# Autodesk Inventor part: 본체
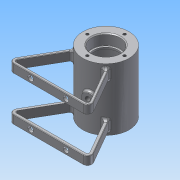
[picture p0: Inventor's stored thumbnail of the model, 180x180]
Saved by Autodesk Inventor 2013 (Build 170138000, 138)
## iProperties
Created: 2016-03
Part Number: 본체
Material: 알루미늄 6061
Document SubType Name: Modeling
Designer: Administrator
Density: 2.71 g/cm^3
Mass: 216.047 g
Surface Area: 342.935 cm^2
Volume: 79.7221 cm^3
Author: Administrator
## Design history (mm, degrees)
sketch "스케치1"
  geometry: C1 r 26 at (0, 0); 1 further point
  constraints: 1 centre point, 1 coincident
  dimensions: "d0" = 52 diameter of C1
extrude "돌출1" new body sketch "스케치1" stored distance "d1" = 70; taper "d2" = 0 deg
node "작업 평면1"
sketch "스케치2"
  geometry: L1 (0, 0)-(0, -62); L2 (-42.594, -62)-(42.594, -62); L3 (42.594, -62)-(0, 11.775); L4 (-42.594, -62)-(0, 11.775); C1 r 26 at (0, 0) reference; 1 further point
  constraints: 8 end point, 1 midpoint, 1 perpendicular, 1 vertical, 1 other
  dimensions: "d6" = 62 distance of L1.start L1.end; "d7" = 60 deg angle of L2 L3; "d8" = 85.18802 distance of L2.start L2.end
feature "리브1" sketch "스케치2" dims "d9" = 3, "d10" = 10, "d11" = 0, "d12" = 0, "d13" = 1, "d14" = 1
sketch "스케치3"
  geometry: C1 r 26 at (0, 0) reference; C2 r 21 at (0, 0); 1 further point
  constraints: 1 centre point, 1 coincident
  dimensions: "d15" = 42 diameter of C2
extrude "돌출2" cut sketch "스케치3" stored distance "d16" = 42; taper "d17" = 0 deg
sketch "스케치4"
  geometry: C1 r 26 at (0, 0) reference; C2 r 16 at (0, 0)
  constraints: 1 centre point, 1 coincident
  dimensions: "d18" = 32 diameter of C2
extrude "돌출3" cut sketch "스케치4" distance "d19" = 12; taper "d20" = 0 deg
sketch "스케치5"
  geometry: C1 r 16 at (0, 0) reference; C2 r 14 at (0, 0)
  constraints: 1 centre point, 1 coincident
  dimensions: "d21" = 28 diameter of C2
extrude "돌출4" cut sketch "스케치5" stored distance "d22" = 12; taper "d23" = 0 deg
node "작업 평면2"
sketch "스케치6"
  geometry: C1 r 5 at (0, 0); 1 further point
  constraints: 1 centre point, 1 coincident
  dimensions: "d25" = 10 diameter of C1
extrude "돌출5" join sketch "스케치6" stored distance "d26" = 12; taper "d27" = 0 deg
sketch "스케치7"
  geometry: L1 (-5, 25.515)-(-5, 29) reference; L2 (-5, 29)-(5, 29) reference; L3 (5, 29)-(5, 25.515) reference; L4 (0, 0)-(7.506, -28.012); L5 (0, 0)-(0, -50.543); C1 r 21 at (0, 0) reference; A1 r 26 centre (0, 0) between (-5, 25.515) and (5, 25.515) reference; 1 further point
  constraints: 4 end point, 1 parallel
  dimensions: "d28" = 29 distance of L4.start L4.end; "d29" = 15 deg angle of L4 L5
  node "절단 모서리 투영3"
node "작업 평면3"
sketch "스케치8"
  geometry: C1 r 6 at (0, 0); 1 further point
  constraints: 1 centre point, 1 coincident
  dimensions: "d30" = 12 diameter of C1
extrude "돌출6" join sketch "스케치8" stored distance "d31" = 12; taper "d32" = 0 deg
node "작업 평면4"
sketch "스케치9"
  geometry: L1 (-26, -35)-(-26, 35) reference; 2 further points
  constraints: 1 coincident, 1 other
feature "엠보싱1" sketch "스케치9" dims "d34" = 0.5, "d35" = 0
sketch "스케치10"
  geometry: C1 r 14 at (0, 0) reference; 1 further point
  constraints: 1 vertical alignment
  dimensions: "d36" = 21 distance of C1.centre point (0, 21)
hole "구멍1" sketch "스케치10" at (0, 21) diameter "d37" = 3.242; stored, may be unused: countersink angle "d41" = 90 deg, drill point angle "d43" = 118 deg; dims "d38" = 8, "d39" = 4, "d40" = 2, "d42" = 10
sketch "스케치11"
  geometry: C1 r 5 at (0, 0) reference
hole "구멍2" sketch "스케치11" at (0, 0) diameter "d47" = 5.188; stored, may be unused: countersink angle "d51" = 90 deg, drill point angle "d53" = 0 deg; dims "d48" = 50, "d49" = 4, "d50" = 2, "d52" = 10
sketch "스케치12"
  geometry: C1 r 6 at (0, 0) reference
hole "구멍3" sketch "스케치12" at (0, 0) diameter "d54" = 5.188; stored, may be unused: countersink angle "d58" = 90 deg, drill point angle "d60" = 0 deg; dims "d55" = 50, "d56" = 4, "d57" = 2, "d59" = 10
sketch "스케치13"
  geometry: 1 further point
fillet "모깎기1" dims "d61" = 3, "d62" = 0.3, "d63" = 5
fillet "모깎기2" dims "d64" = 2
sketch "스케치14"
  geometry: L1 (78.26, 0)-(0, 0) reference; L2 (0, 10)-(78.26, 10) reference; C1 r 3 at (19.13, 5); C2 r 3 at (59.13, 5); 1 further point
  constraints: 2 centre point
  dimensions: "d65" = 6 diameter of C1; "d66" = 6 diameter of C2; "d67" = 20 horizontal distance of point (39.13, -20) C1.centre; "d68" = 40 distance of C2.centre C1.centre; "d69" = 5 distance from line of C1.centre L2; "d70" = 5 distance from line of L1 C2.centre
extrude "돌출7" cut sketch "스케치14" stored distance "d71" = 12; taper "d72" = 0 deg
chamfer "모따기1" distance "d73" = 1; stored, may be unused: second distance "d74" = 2, angle "d75" = 45 deg
fillet "모깎기3" dims "d76" = 0.5
fillet "모깎기4" dims "d77" = 3
fillet "모깎기5" dims "d78" = 2
fillet "모깎기6" dims "d79" = 2
node "솔리드1"
mirror "대칭1"
pattern_circular "원형 패턴1" dims angle "d45" = 360 deg
mirror "대칭2"
mirror "대칭3"
mirror "대칭4"
node "절단 모서리 투영1"
node "절단 모서리 투영2"
other parameters: "d24" = 29, "d33" = -26
